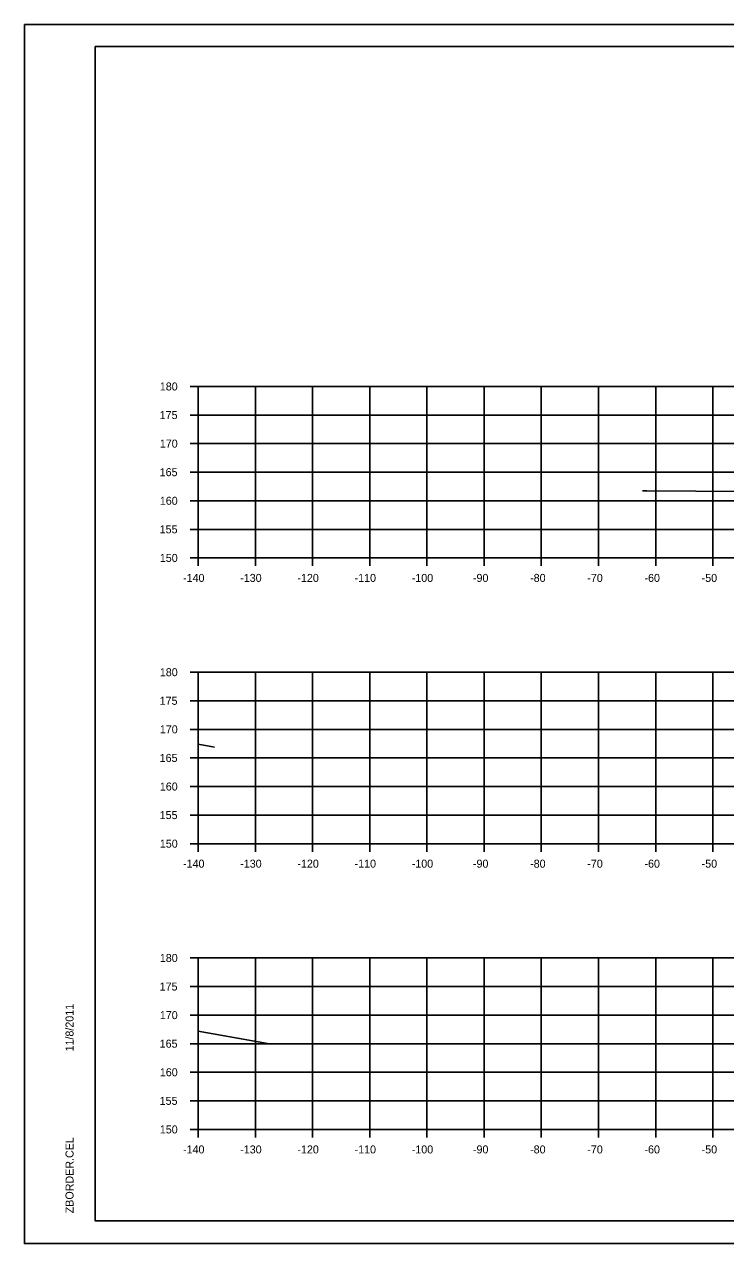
# Model space of a CAD drawing. Extents: x 1368503 to 1373085, y 379840 to 381833.
# Drawn here: x 1372751.7 to 1372874.3, y 381028.3 to 381241.7 of the extents above; entities that cross this region are included whole.
import ezdxf

# ---------------------------------------------------------------- set-up
doc = ezdxf.new("R2010")
doc.units = 0
for name, color, linetype in [('S_BRIDGE', 7, 'Continuous'), ('S_EDGE_PAVEMENT', 7, 'Continuous'), ('S_MISC_BOUNDARY', 7, 'Continuous'), ('S_PHOTO_CENTERS', 7, 'Continuous'), ('S_PHOTO_NOTES', 7, 'Continuous'), ('S_TRAILS', 7, 'Continuous')]:
    doc.layers.add(name, color=color, linetype=linetype)

msp = doc.modelspace()

# ---------------------------------------------------------------- linework, layer by layer
at = {"layer": 'S_BRIDGE'}
for p, q in [((1372764.08, 381237.76), (1373080.26, 381237.76)), ((1372764.08, 381032.3), (1372764.08, 381237.76)), ((1372764.08, 381032.3), (1372764.08, 381032.3)), ((1373080.26, 381032.3), (1372764.08, 381032.3))]:
    msp.add_line(p, q, dxfattribs=at)
at = {"layer": 'S_EDGE_PAVEMENT'}
for p, q in [((1372780.68, 381178.3), (1372782.08, 381178.3)), ((1372782.08, 381148.3), (1372782.08, 381178.3)), ((1372780.68, 381173.3), (1372782.08, 381173.3)), ((1372780.68, 381168.3), (1372782.08, 381168.3)), ((1372780.68, 381163.3), (1372782.08, 381163.3)), ((1372780.68, 381158.3), (1372782.08, 381158.3)), ((1372780.68, 381153.3), (1372782.08, 381153.3)), ((1372780.68, 381148.3), (1372782.08, 381148.3)), ((1372782.08, 381148.3), (1373062.08, 381148.3)), ((1372782.08, 381146.9), (1372782.08, 381148.3)), ((1372792.08, 381146.9), (1372792.08, 381148.3)), ((1372802.08, 381146.9), (1372802.08, 381148.3)), ((1372812.08, 381146.9), (1372812.08, 381148.3)), ((1372822.08, 381146.9), (1372822.08, 381148.3)), ((1372832.08, 381146.9), (1372832.08, 381148.3)), ((1372842.08, 381146.9), (1372842.08, 381148.3)), ((1372852.08, 381146.9), (1372852.08, 381148.3)), ((1372862.08, 381146.9), (1372862.08, 381148.3)), ((1372872.08, 381146.9), (1372872.08, 381148.3)), ((1372780.68, 381128.3), (1372782.08, 381128.3)), ((1372782.08, 381098.3), (1372782.08, 381128.3)), ((1372780.68, 381123.3), (1372782.08, 381123.3)), ((1372780.68, 381118.3), (1372782.08, 381118.3)), ((1372780.68, 381113.3), (1372782.08, 381113.3)), ((1372780.68, 381108.3), (1372782.08, 381108.3)), ((1372780.68, 381103.3), (1372782.08, 381103.3)), ((1372780.68, 381098.3), (1372782.08, 381098.3)), ((1372782.08, 381098.3), (1373062.08, 381098.3)), ((1372782.08, 381096.9), (1372782.08, 381098.3)), ((1372792.08, 381096.9), (1372792.08, 381098.3)), ((1372802.08, 381096.9), (1372802.08, 381098.3)), ((1372812.08, 381096.9), (1372812.08, 381098.3)), ((1372822.08, 381096.9), (1372822.08, 381098.3)), ((1372832.08, 381096.9), (1372832.08, 381098.3)), ((1372842.08, 381096.9), (1372842.08, 381098.3)), ((1372852.08, 381096.9), (1372852.08, 381098.3)), ((1372862.08, 381096.9), (1372862.08, 381098.3)), ((1372872.08, 381096.9), (1372872.08, 381098.3)), ((1372780.68, 381078.3), (1372782.08, 381078.3)), ((1372782.08, 381048.3), (1372782.08, 381078.3)), ((1372780.68, 381073.3), (1372782.08, 381073.3)), ((1372780.68, 381068.3), (1372782.08, 381068.3)), ((1372780.68, 381063.3), (1372782.08, 381063.3)), ((1372780.68, 381058.3), (1372782.08, 381058.3)), ((1372780.68, 381053.3), (1372782.08, 381053.3)), ((1372780.68, 381048.3), (1372782.08, 381048.3)), ((1372782.08, 381048.3), (1373062.08, 381048.3)), ((1372782.08, 381046.9), (1372782.08, 381048.3)), ((1372792.08, 381046.9), (1372792.08, 381048.3)), ((1372802.08, 381046.9), (1372802.08, 381048.3)), ((1372812.08, 381046.9), (1372812.08, 381048.3)), ((1372822.08, 381046.9), (1372822.08, 381048.3)), ((1372832.08, 381046.9), (1372832.08, 381048.3)), ((1372842.08, 381046.9), (1372842.08, 381048.3)), ((1372852.08, 381046.9), (1372852.08, 381048.3)), ((1372862.08, 381046.9), (1372862.08, 381048.3)), ((1372872.08, 381046.9), (1372872.08, 381048.3))]:
    msp.add_line(p, q, dxfattribs=at)
at = {"layer": 'S_MISC_BOUNDARY'}
for points in [[(1372859.76, 381160.05), (1372860.53, 381160.05), (1372877.68, 381159.92)], [(1372782.08, 381115.72), (1372784.94, 381115.2)], [(1372782.08, 381065.5), (1372794.18, 381063.31)]]:
    msp.add_lwpolyline(points, dxfattribs=at)
at = {"layer": 'S_PHOTO_CENTERS'}
for p, q in [((1372782.08, 381178.3), (1373062.08, 381178.3)), ((1372782.08, 381148.3), (1372782.08, 381178.3)), ((1372792.08, 381148.3), (1372792.08, 381178.3)), ((1372802.08, 381148.3), (1372802.08, 381178.3)), ((1372812.08, 381148.3), (1372812.08, 381178.3)), ((1372822.08, 381148.3), (1372822.08, 381178.3)), ((1372832.08, 381148.3), (1372832.08, 381178.3)), ((1372842.08, 381148.3), (1372842.08, 381178.3)), ((1372852.08, 381148.3), (1372852.08, 381178.3)), ((1372862.08, 381148.3), (1372862.08, 381178.3)), ((1372872.08, 381148.3), (1372872.08, 381178.3)), ((1372782.08, 381173.3), (1373062.08, 381173.3)), ((1372782.08, 381168.3), (1373062.08, 381168.3)), ((1372782.08, 381163.3), (1373062.08, 381163.3)), ((1372782.08, 381158.3), (1373062.08, 381158.3)), ((1372782.08, 381153.3), (1373062.08, 381153.3)), ((1372782.08, 381148.3), (1373062.08, 381148.3)), ((1372782.08, 381128.3), (1373062.08, 381128.3)), ((1372782.08, 381098.3), (1372782.08, 381128.3)), ((1372782.08, 381128.3), (1373062.08, 381128.3)), ((1372782.08, 381098.3), (1372782.08, 381128.3)), ((1372792.08, 381098.3), (1372792.08, 381128.3)), ((1372792.08, 381098.3), (1372792.08, 381128.3)), ((1372802.08, 381098.3), (1372802.08, 381128.3)), ((1372802.08, 381098.3), (1372802.08, 381128.3)), ((1372812.08, 381098.3), (1372812.08, 381128.3)), ((1372812.08, 381098.3), (1372812.08, 381128.3)), ((1372822.08, 381098.3), (1372822.08, 381128.3)), ((1372822.08, 381098.3), (1372822.08, 381128.3)), ((1372832.08, 381098.3), (1372832.08, 381128.3)), ((1372832.08, 381098.3), (1372832.08, 381128.3)), ((1372842.08, 381098.3), (1372842.08, 381128.3)), ((1372842.08, 381098.3), (1372842.08, 381128.3)), ((1372852.08, 381098.3), (1372852.08, 381128.3)), ((1372852.08, 381098.3), (1372852.08, 381128.3)), ((1372862.08, 381098.3), (1372862.08, 381128.3)), ((1372862.08, 381098.3), (1372862.08, 381128.3)), ((1372872.08, 381098.3), (1372872.08, 381128.3)), ((1372872.08, 381098.3), (1372872.08, 381128.3)), ((1372782.08, 381123.3), (1373062.08, 381123.3)), ((1372782.08, 381123.3), (1373062.08, 381123.3)), ((1372782.08, 381118.3), (1373062.08, 381118.3)), ((1372782.08, 381118.3), (1373062.08, 381118.3)), ((1372782.08, 381113.3), (1373062.08, 381113.3)), ((1372782.08, 381113.3), (1373062.08, 381113.3)), ((1372782.08, 381108.3), (1373062.08, 381108.3)), ((1372782.08, 381108.3), (1373062.08, 381108.3)), ((1372782.08, 381103.3), (1373062.08, 381103.3)), ((1372782.08, 381103.3), (1373062.08, 381103.3)), ((1372782.08, 381098.3), (1373062.08, 381098.3)), ((1372782.08, 381098.3), (1373062.08, 381098.3)), ((1372782.08, 381078.3), (1373062.08, 381078.3)), ((1372782.08, 381048.3), (1372782.08, 381078.3)), ((1372782.08, 381078.3), (1373062.08, 381078.3)), ((1372782.08, 381048.3), (1372782.08, 381078.3)), ((1372792.08, 381048.3), (1372792.08, 381078.3)), ((1372792.08, 381048.3), (1372792.08, 381078.3)), ((1372802.08, 381048.3), (1372802.08, 381078.3)), ((1372802.08, 381048.3), (1372802.08, 381078.3)), ((1372812.08, 381048.3), (1372812.08, 381078.3)), ((1372812.08, 381048.3), (1372812.08, 381078.3)), ((1372822.08, 381048.3), (1372822.08, 381078.3)), ((1372822.08, 381048.3), (1372822.08, 381078.3)), ((1372832.08, 381048.3), (1372832.08, 381078.3)), ((1372832.08, 381048.3), (1372832.08, 381078.3)), ((1372842.08, 381048.3), (1372842.08, 381078.3)), ((1372842.08, 381048.3), (1372842.08, 381078.3)), ((1372852.08, 381048.3), (1372852.08, 381078.3)), ((1372852.08, 381048.3), (1372852.08, 381078.3)), ((1372862.08, 381048.3), (1372862.08, 381078.3)), ((1372862.08, 381048.3), (1372862.08, 381078.3)), ((1372872.08, 381048.3), (1372872.08, 381078.3)), ((1372872.08, 381048.3), (1372872.08, 381078.3)), ((1372782.08, 381073.3), (1373062.08, 381073.3)), ((1372782.08, 381073.3), (1373062.08, 381073.3)), ((1372782.08, 381068.3), (1373062.08, 381068.3)), ((1372782.08, 381068.3), (1373062.08, 381068.3)), ((1372782.08, 381063.3), (1373062.08, 381063.3)), ((1372782.08, 381063.3), (1373062.08, 381063.3)), ((1372782.08, 381058.3), (1373062.08, 381058.3)), ((1372782.08, 381058.3), (1373062.08, 381058.3)), ((1372782.08, 381053.3), (1373062.08, 381053.3)), ((1372782.08, 381053.3), (1373062.08, 381053.3)), ((1372782.08, 381048.3), (1373062.08, 381048.3)), ((1372782.08, 381048.3), (1373062.08, 381048.3))]:
    msp.add_line(p, q, dxfattribs=at)
at = {"layer": 'S_PHOTO_NOTES'}
for p, q in [((1372751.68, 381241.66), (1373085.01, 381241.66)), ((1372751.68, 381028.32), (1373085.01, 381028.32))]:
    msp.add_line(p, q, dxfattribs=at)
for points in [[(1372751.67, 381241.66), (1373085.01, 381241.66), (1373085.01, 381028.32), (1372751.67, 381028.32)], [(1372998, 381237.76), (1372998, 381227.88), (1373033.73, 381227.88), (1373033.73, 381224.96), (1373056.93, 381224.96), (1373056.93, 381200.63), (1373080.26, 381200.63), (1373080.26, 381032.3), (1372764.08, 381032.3), (1372764.08, 381237.76)]]:
    msp.add_lwpolyline(points, close=True, dxfattribs=at)

# ---------------------------------------------------------------- texts
at = {"layer": 'S_BRIDGE'}
for s, p in [('11/8/2011', (1372760.27, 381061.94)), ('ZBORDER.CEL', (1372760.27, 381033.63))]:
    msp.add_text(s, height=1.4, rotation=90, dxfattribs=at).set_placement(p)
at = {"layer": 'S_TRAILS'}
for s, p in [('180', (1372775.36, 381177.6)), ('175', (1372775.33, 381172.6)), ('170', (1372775.36, 381167.6)), ('165', (1372775.33, 381162.6)), ('160', (1372775.36, 381157.6)), ('155', (1372775.33, 381152.6)), ('150', (1372775.36, 381147.6)), ('-140', (1372779.42, 381144.1)), ('-130', (1372789.42, 381144.1)), ('-120', (1372799.42, 381144.1)), ('-110', (1372809.42, 381144.1)), ('-100', (1372819.42, 381144.1)), ('-90', (1372830.12, 381144.1)), ('-80', (1372840.12, 381144.1)), ('-70', (1372850.12, 381144.1)), ('-60', (1372860.12, 381144.1)), ('-50', (1372870.12, 381144.1)), ('180', (1372775.36, 381127.6)), ('175', (1372775.33, 381122.6)), ('170', (1372775.36, 381117.6)), ('165', (1372775.33, 381112.6)), ('160', (1372775.36, 381107.6)), ('155', (1372775.33, 381102.6)), ('150', (1372775.36, 381097.6)), ('-140', (1372779.42, 381094.1)), ('-130', (1372789.42, 381094.1)), ('-120', (1372799.42, 381094.1)), ('-110', (1372809.42, 381094.1)), ('-100', (1372819.42, 381094.1)), ('-90', (1372830.12, 381094.1)), ('-80', (1372840.12, 381094.1)), ('-70', (1372850.12, 381094.1)), ('-60', (1372860.12, 381094.1)), ('-50', (1372870.12, 381094.1)), ('180', (1372775.36, 381077.6)), ('175', (1372775.33, 381072.6)), ('170', (1372775.36, 381067.6)), ('165', (1372775.33, 381062.6)), ('160', (1372775.36, 381057.6)), ('155', (1372775.33, 381052.6)), ('150', (1372775.36, 381047.6)), ('-140', (1372779.42, 381044.1)), ('-130', (1372789.42, 381044.1)), ('-120', (1372799.42, 381044.1)), ('-110', (1372809.42, 381044.1)), ('-100', (1372819.42, 381044.1)), ('-90', (1372830.12, 381044.1)), ('-80', (1372840.12, 381044.1)), ('-70', (1372850.12, 381044.1)), ('-60', (1372860.12, 381044.1)), ('-50', (1372870.12, 381044.1))]:
    msp.add_text(s, height=1.4, dxfattribs=at).set_placement(p)

doc.saveas('drawing.dxf')
